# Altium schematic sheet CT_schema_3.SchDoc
size 204 x 169 mm
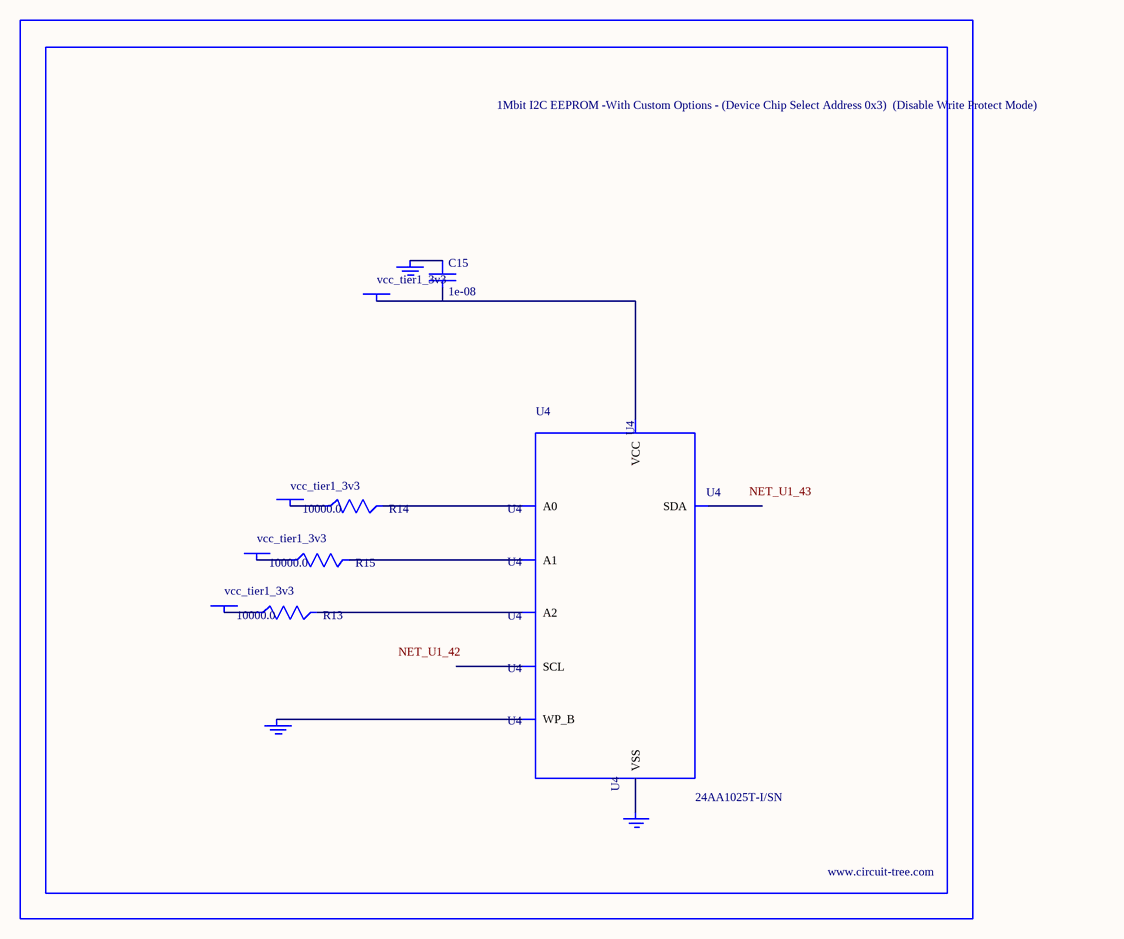
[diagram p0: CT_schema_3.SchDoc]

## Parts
BORDER2  (no value)
C15  1e-08  [C0402]
GND_INSTANCE_2_0  (no value)
GND_INSTANCE_2_1  (no value)
GND_INSTANCE_2_2  (no value)
POWER_INSTANCE_2_0  vcc_tier1_3v3
POWER_INSTANCE_2_1  vcc_tier1_3v3
POWER_INSTANCE_2_2  vcc_tier1_3v3
POWER_INSTANCE_2_3  vcc_tier1_3v3
R13  10000.0  [R0603]
R14  10000.0  [R0603]
R15  10000.0  [R0603]
U4  24AA1025T-I/SN  [SOIC-8]

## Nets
NetC15_1: C15.1 GND_INSTANCE_2_1.0(GND)
NetC15_2: C15.2 POWER_INSTANCE_2_3.0(PWR) U4.8(VCC)
NetGND_INSTANCE_2_0_0: GND_INSTANCE_2_0.0(GND) U4.7(WP_B)
NetGND_INSTANCE_2_2_0: GND_INSTANCE_2_2.0(GND) U4.4(VSS)
NetPOWER_INSTANCE_2_0_0: POWER_INSTANCE_2_0.0(PWR) R14.1
NetPOWER_INSTANCE_2_1_0: POWER_INSTANCE_2_1.0(PWR) R15.1
NetPOWER_INSTANCE_2_2_0: POWER_INSTANCE_2_2.0(PWR) R13.1
NetR13_2: R13.2 U4.3(A2)
NetR14_2: R14.2 U4.1(A0)
NetR15_2: R15.2 U4.2(A1)

Not connected (* = marked no-connect by the designer): U4 5(SDA) 6(SCL)

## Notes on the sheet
- Labels drawn without touching a wire or pin: NET_U1_42, NET_U1_43

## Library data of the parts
BORDER2 = BORDER_PAGE2
C15 = C0402C103K3RAC
GND_INSTANCE_2_0-GND_INSTANCE_2_2 = GND
POWER_INSTANCE_2_0-POWER_INSTANCE_2_3 = PWR
R13-R15 = RC0603JR-0710KL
